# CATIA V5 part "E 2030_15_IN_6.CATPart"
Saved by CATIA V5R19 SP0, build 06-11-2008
Material "Plastic": density 1200 kg/m3, Young's modulus 2.2e+09 Pa, Poisson ratio 0.38, thermal expansion 6.84e-05 1/K
Bounding box of the stored display mesh (mm): x 15.1 to 30.2, y -30.19 to -15.11, z -2 to 0
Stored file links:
  G:\UTB\Kombinované\Bakalářská práce\Catia\FORMA\E 2030_15_IN_6.CATPart
  D:\Aplikace\CATIA\Nová složka\win_b64\startup\materials\Catalog.CATMaterial
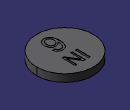
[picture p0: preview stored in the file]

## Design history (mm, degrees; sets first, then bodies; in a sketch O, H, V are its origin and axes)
Body1 "E 2030_15_IN_1-8" (main body)
  Solid1: solid without history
